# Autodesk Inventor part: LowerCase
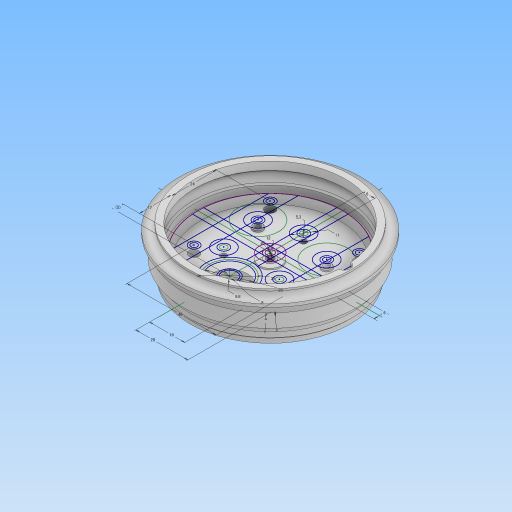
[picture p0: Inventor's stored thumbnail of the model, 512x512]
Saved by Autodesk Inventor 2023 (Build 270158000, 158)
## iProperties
Created: 2024-05
Part Number: LowerCase
Material: 一般
Document SubType Name: Modeling
Designer: kumagai
Density: 1 g/cm^3
Appearance: 既定
Author: kumagai
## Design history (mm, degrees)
derived "CoreSketch.ipt"
  sketch "Vertical"
    geometry: L1 (0, 65.337)-(0, -65.337) reference; L2 (-46.2, 0)-(46.2, 0) reference; L3 (-11, 2)-(11, 2) reference; L4 (11, 2)-(11, -2) reference; L5 (11, -2)-(-11, -2) reference; L6 (-11, -2)-(-11, 2) reference; L7 (11, 2)-(33, 2) reference; L8 (33, 2)-(33, -2) reference; L9 (33, -2)-(11, -2) reference; L10 (11, -2)-(11, 2) reference; L11 (22, 2.772)-(22, -2.683) reference; L12 (-33, 2)-(-11, 2) reference; L13 (-11, 2)-(-11, -2) reference; L14 (-11, -2)-(-33, -2) reference; L15 (-33, -2)-(-33, 2) reference; L16 (-22, 4.087)-(-22, -4.199) reference; L17 (-33, 10)-(-11, 10) reference; L18 (-11, 10)-(-11, 6) reference; L19 (-11, 6)-(-33, 6) reference; L20 (-33, 6)-(-33, 10) reference; L21 (-27.353, 10)-(-16.647, 10) reference; L22 (-16.647, 10)-(-16.647, 16) reference; L23 (-16.647, 16)-(-27.353, 16) reference; L24 (-27.353, 16)-(-27.353, 10) reference; L25 (11, 16)-(33, 16) reference; L26 (33, 16)-(33, 12) reference; L27 (33, 12)-(11, 12) reference; L28 (11, 12)-(11, 16) reference; L29 (16.134, 12)-(27.866, 12) reference; L30 (27.866, 12)-(27.866, 6) reference; L31 (27.866, 6)-(16.134, 6) reference; L32 (16.134, 6)-(16.134, 12) reference; L33 (-22, 18.272)-(-22, 9.031) reference; L34 (22, 22.635)-(22, 12.71) reference; L35 (33, -2)-(35, -2) reference; L36 (35, -2)-(35, 10) reference; L37 (35, 10)-(33, 10) reference; L38 (33, 10)-(33, -2) reference; L39 (0, -4)-(37.5, -4) reference; L40 (40.5, -1)-(40.5, 14) reference; L41 (43.9, -8)-(0, -8) reference; L42 (0, -4)-(0, -8) reference; L43 (35, -2)-(39, -2) reference; L44 (39, -2)-(39, 3.066) reference; L45 (38.45, 8.685)-(41.471, 10.429) reference; L46 (38.45, 10)-(35, 10) reference; L47 (40.5, 9.627)-(41.993, 8.375) reference; L48 (41.55, 3.315)-(40.5, 2.709) reference; L49 (37.5, -4)-(40.5, -1) reference; L50 (-43, 43.294)-(-1, 43.294) reference; L51 (-1, 43.294)-(-1, 26) reference; L52 (-1, 26)-(-43, 26) reference; L53 (-43, 26)-(-43, 43.294) reference; L54 (1, 43.294)-(43, 43.294) reference; L55 (43, 43.294)-(43, 26) reference; L56 (43, 26)-(1, 26) reference; L57 (1, 26)-(1, 43.294) reference; L58 (-22, 45.556)-(-22, 31.232) reference; L59 (22, 47.214)-(22, 32.287) reference; L60 (48, 5.268)-(48, -2.616) reference; L61 (43.6, -11)-(54, -11) reference; L62 (54, -11)-(54, 18) reference; L63 (45.222, -3.461)-(46.5, -2.566) reference; L64 (48, -2.616)-(49.192, -3.808) reference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; A1 r 3.1 centre (40, 6) between (39, 3.066) and (38.45, 8.685) reference; A2 r 3.1 centre (47, -6) between (45.222, -3.461) and (49.192, -3.808) reference; A3 r 3.1 centre (47, 13) between (43.9, 13) and (49, 10.631) reference; 3 further points; 1 other entity
    constraints: 6 end point, 2 collinear, 1 point on line, 1 other
    dimensions: "d15" = 4 distance between parallel lines of L91 L41
  sketch "PlanetaryGears"
    geometry: L1 (0, -14)-(0, 14) reference; L2 (-14, 0)-(14, 0) reference; L3 (-32.742, -21.042)-(-37.024, -23.794) reference; C1 r 33 at (0, 0) reference; C2 r 11 at (0, 0) reference; C3 r 11 at (22, 0) reference; C4 r 11 at (-22, 0) reference; C5 r 11 at (0, 22) reference; C6 r 11 at (-18.508, -11.894) reference; C7 r 11 at (18.508, -11.894) reference; C8 r 1.65 at (15, 10) reference; C9 r 1.65 at (-15, 10) reference; C10 r 1.65 at (0, -18) reference; 1 further point
revolve "回転1" stored, may be unused: angle "d1" = 360 deg
revolve "回転2" stored, may be unused: angle "d2" = 90 deg
fillet "フィレット2" dims "d9" = 0.5
sketch "スケッチ5"
  geometry: L1 (0, -60.2)-(0, 60.2) reference; L2 (-60.2, 0)-(60.2, 0) reference; L3 (-19, 34.059)-(-19, -34.059); L4 (-28, 27.148)-(-28, -27.148); L5 (-3, 38.884)-(-3, 34.135); L6 (-3, 9.865)-(-3, -38.884); L7 (3, 38.884)-(3, 34.135); L8 (3, 9.865)-(3, -38.884); L9 (28, 27.148)-(28, -27.148); L10 (19, 34.059)-(19, -34.059); L11 (-38.884, 3)-(38.884, 3); L12 (-38.884, -3)-(38.884, -3); C1 r 11 at (0, 22) reference; C2 r 10 at (0, 22); C3 r 4.9 at (0, 22); C4 r 4 at (0, 22); C5 r 1.65 at (-15, 10) reference; C6 r 1.65 at (15, 10) reference; C7 r 1.65 at (0, -18) reference; C8 r 11 at (-18.508, -11.894) reference; C9 r 11 at (18.508, -11.894) reference; C10 r 1.65 at (-18.508, -11.894); C11 r 1.65 at (18.508, -11.894); C12 r 5.5 at (-18.508, -11.894); C13 r 5.5 at (0, -18); C14 r 5.5 at (18.508, -11.894); C15 r 5.5 at (-15, 10); C16 r 5.5 at (15, 10); C17 r 2.65 at (-15, 10); C18 r 2.65 at (-18.508, -11.894); C19 r 2.65 at (0, -18); C20 r 2.65 at (18.508, -11.894); C21 r 2.65 at (15, 10); C22 r 43 at (0, 0) reference; C23 r 42 at (0, 0); C24 r 6 at (0, 0); C25 r 2 at (0, 0); C26 r 3 at (0, 0); C27 r 1.65 at (24, 17); C28 r 1.65 at (-24, 17); C29 r 1.65 at (24, -24); C30 r 1.65 at (-24, -24); C31 r 2.65 at (24, -24); C32 r 2.65 at (24, 17); C33 r 2.65 at (-24, -24); C34 r 2.65 at (-24, 17); A1 r 12.5 centre (0, 22) between (-3, 34.135) and (-3, 9.865); 36 further points
  constraints: 28 centre point, 24 coincident, 20 end point, 16 equal radius, 4 point on circle, 4 point on line, 1 horizontal, 1 vertical alignment, 24 other
  dimensions: "d14" = 20 diameter of C2; "d16" = 25 diameter of A1; "d21" = 9.8 diameter of C3; "d24" = 8 diameter of C4; "d27" = 11 diameter of C13; "d28" = 5.3 diameter of C19; "d34" = 1 radial gap between concentric circles of C23 C22; "d35" = 3 dimension on C23; "d36" = 19 distance between parallel lines of L1 L3; "d37" = 28 distance between parallel lines of L1 L4; "d38" = 6 distance between parallel lines of L8 L6; "d39" = 6 distance between parallel lines of L12 L11; "d42" = 12 diameter of C24; "d43" = 4 diameter of C25; "d44" = 6 diameter of C26; "d56" = 48 distance of C28.centre C27.centre; "d58" = 17 distance from line of C27.centre L2; "d59" = 5 vertical distance of C27.centre C1.centre (derived); "d60" = 24 distance from line of L2 C29.centre
  node "投影ループ1"
extrude "押し出し1" join sketch "スケッチ5" stored distance "d17" = 7; taper "d18" = 0 deg
extrude "押し出し2" cut sketch "スケッチ5" stored distance "d19" = 4.5; taper "d20" = 0 deg
extrude "押し出し3" cut sketch "スケッチ5" stored distance "d22" = 4.8; taper "d23" = 0 deg
extrude "押し出し4" cut sketch "スケッチ5" extent not by distance; stored distance "d25" = 0; taper "d26" = 0 deg
extrude "押し出し5" cut sketch "スケッチ5" stored distance "d29" = 4.5; taper "d30" = 0 deg
chamfer "面取り1" distance "d31" = 1; stored, may be unused: second distance "d32" = 2, angle "d33" = 45 deg
extrude "押し出し6" join sketch "スケッチ5" stored distance "d40" = 1.2; taper "d41" = 0 deg
chamfer "面取り2" distance "d45" = 0.4; stored, may be unused: second distance "d46" = 2, angle "d47" = 45 deg
extrude "押し出し7" join sketch "スケッチ5" stored distance "d48" = 0.8; taper "d49" = 0 deg
chamfer "面取り3" distance "d50" = 1.5; stored, may be unused: second distance "d51" = 2, angle "d52" = 45 deg
sketch "スケッチ6"
  geometry: C1 r 1 at (8.235, 1.37); 1 further point
  constraints: 1 centre point
  dimensions: "d53" = 2 diameter of C1
extrude "押し出し8" join sketch "スケッチ6" stored distance "d54" = 7; taper "d55" = 0 deg
extrude "押し出し9" cut sketch "スケッチ5" stored distance "d61" = 5; taper "d62" = 0 deg
node "ソリッド1"
sketch "スケッチ3"
  geometry: L1 (38.45, 10)-(35, 10) reference; L2 (40, 6)-(40, 15.1); L3 (40, 6)-(43.1, 6); L4 (43.1, 6)-(43.1, 12); L5 (43.039, 13.648)-(45.279, 12.064); A1 r 3.1 centre (40, 12) between (43.1, 12) and (40, 15.1); 2 further points
  constraints: 8 end point, 2 point on circle, 2 point on line, 2 tangent, 2 vertical, 1 centre point, 1 horizontal, 1 horizontal alignment, 1 other
  dimensions: "d5" = 1.55 distance from line of point (38.45, 10) L2; "d7" = 2 distance from line of L1 A1.centre; "d8" = 5.62789 distance from line of L5 point (38.45, 10)
